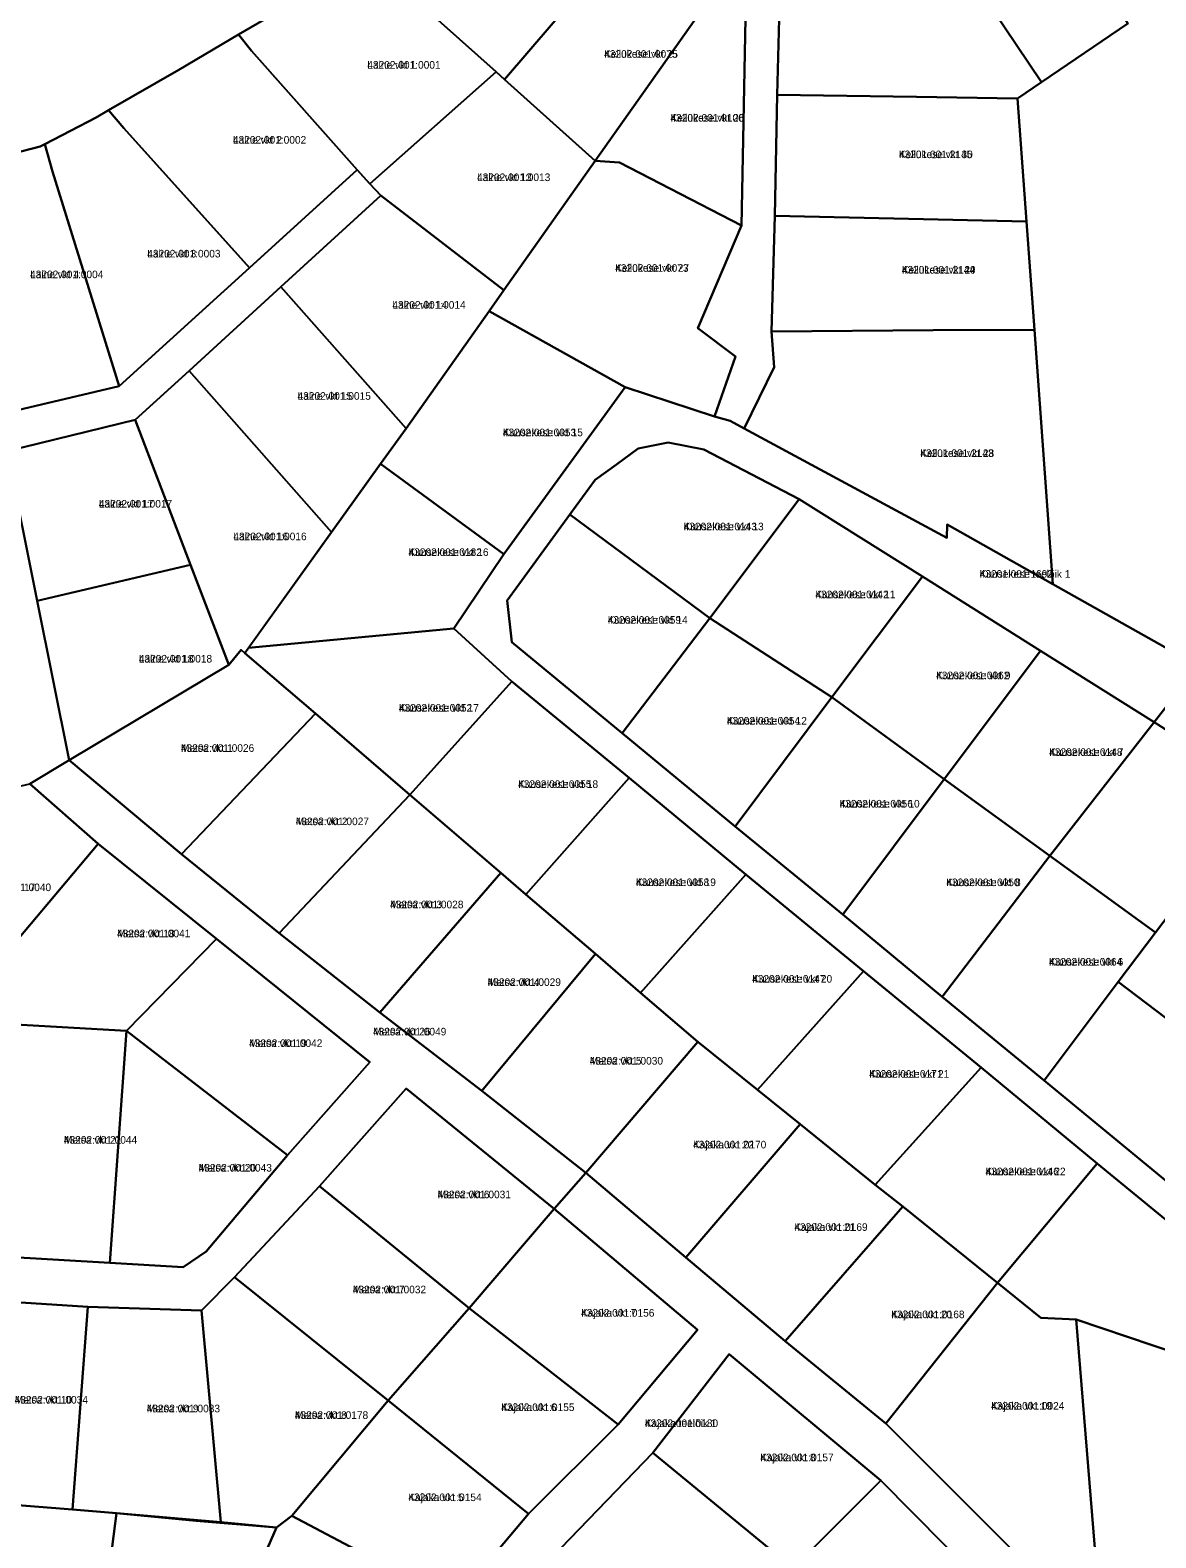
# Model space of a CAD drawing. Extents: x 661852 to 683758, y 6469495 to 6482657.
# Drawn here: x 665584.5 to 665807.3, y 6471214 to 6471512.2 of the extents above; entities that cross this region are included whole.
import ezdxf

# ---------------------------------------------------------------- set-up
doc = ezdxf.new("R2010")
doc.units = 0
for name, color, linetype in [('L_AADRESS', 7, 'Continuous'), ('PIIR', 7, 'Continuous'), ('TUNNUS', 7, 'Continuous')]:
    doc.layers.add(name, color=color, linetype=linetype)

msp = doc.modelspace()

# ---------------------------------------------------------------- linework, layer by layer
at = {"layer": 'PIIR'}
for points in [[(665767.41, 6471527.59), (665747.38, 6471557.17), (665765.56, 6471568.66), (665785.32, 6471538.68), (665801.72, 6471513.57), (665784.67, 6471501.96)], [(665650.95, 6471536.39), (665692.2, 6471535.2), (665697.63, 6471524.99), (665678.39, 6471502.49), (665676.71, 6471503.99), (665654.4, 6471524), (665648.12, 6471529.63)], [(665649.26, 6471484.59), (665628.33, 6471508.17), (665625.77, 6471511.37), (665630.74, 6471514.31), (665642.13, 6471521.05), (665647.12, 6471527.24), (665648.12, 6471529.63), (665654.4, 6471524), (665676.71, 6471503.99), (665651.77, 6471481.85)], [(665732.32, 6471499.43), (665733.06, 6471527.07), (665763.85, 6471523.8), (665767.41, 6471527.59), (665784.67, 6471501.96), (665779.93, 6471498.71), (665759.93, 6471499.05)], [(665706.87, 6471518.76), (665717.83, 6471516.78), (665696.35, 6471486.42), (665678.39, 6471502.49), (665697.63, 6471524.99)], [(665726.1, 6471514.53), (665725.28, 6471473.59), (665701.12, 6471486.1), (665696.35, 6471486.42), (665717.83, 6471516.78)], [(665603.07, 6471492.84), (665600.05, 6471496.41), (665613.96, 6471504.38), (665625.77, 6471511.37), (665628.33, 6471508.17), (665649.26, 6471484.59), (665627.94, 6471465.25)], [(665676.71, 6471503.99), (665678.39, 6471502.49), (665696.35, 6471486.42), (665678.26, 6471460.82), (665653.91, 6471479.55), (665651.77, 6471481.85)], [(665731.9, 6471475.54), (665732.32, 6471499.43), (665759.93, 6471499.05), (665779.93, 6471498.71), (665781.69, 6471474.42), (665761.28, 6471474.89)], [(665588.95, 6471484.26), (665587.44, 6471489.72), (665597.56, 6471494.98), (665600.05, 6471496.41), (665603.07, 6471492.84), (665627.94, 6471465.25), (665602.13, 6471441.82)], [(665567.9, 6471479.65), (665566.88, 6471485.09), (665579.86, 6471487.61), (665580.87, 6471487.8), (665586.53, 6471489.24), (665587.44, 6471489.72), (665588.95, 6471484.26), (665602.13, 6471441.82), (665577.19, 6471435.94)], [(665716.61, 6471453.3), (665724.08, 6471447.73), (665719.92, 6471435.86), (665702.25, 6471441.65), (665675.32, 6471456.68), (665678.26, 6471460.82), (665696.35, 6471486.42), (665701.12, 6471486.1), (665725.28, 6471473.59)], [(665653.91, 6471479.55), (665678.26, 6471460.82), (665675.32, 6471456.68), (665658.92, 6471433.46), (665634.14, 6471461.5)], [(665731.23, 6471452.66), (665731.9, 6471475.54), (665761.28, 6471474.89), (665781.69, 6471474.42), (665783.26, 6471452.99), (665763.19, 6471452.93)], [(665634.14, 6471461.5), (665658.92, 6471433.46), (665653.87, 6471426.44), (665644.14, 6471412.92), (665615.96, 6471444.88)], [(665678.24, 6471408.58), (665653.87, 6471426.44), (665658.92, 6471433.46), (665675.32, 6471456.68), (665702.25, 6471441.65)], [(665731.74, 6471445.57), (665731.23, 6471452.66), (665763.19, 6471452.93), (665783.26, 6471452.99), (665786.91, 6471402.68), (665765.95, 6471414.45), (665765.91, 6471411.86), (665725.82, 6471433.45)], [(665615.96, 6471444.88), (665644.14, 6471412.92), (665626.98, 6471389.05), (665626.3, 6471389.71), (665623.87, 6471386.74), (665616.25, 6471406.48), (665605.33, 6471435.17)], [(665605.33, 6471435.17), (665616.25, 6471406.48), (665585.91, 6471399.37), (665579.99, 6471428.95)], [(665736.69, 6471419.46), (665719, 6471395.91), (665691.34, 6471416.47), (665696.3, 6471423.31), (665700.53, 6471426.35), (665704.86, 6471429.52), (665710.78, 6471430.72), (665717.85, 6471429.29)], [(665678.24, 6471408.58), (665668.35, 6471393.93), (665627.71, 6471390.06), (665644.14, 6471412.92), (665653.87, 6471426.44)], [(665761.08, 6471404.21), (665743.15, 6471380.29), (665719, 6471395.91), (665736.69, 6471419.46)], [(665719, 6471395.91), (665701.64, 6471373.22), (665679.85, 6471391.22), (665678.91, 6471399.42), (665691.34, 6471416.47)], [(665616.25, 6471406.48), (665623.87, 6471386.74), (665592.21, 6471367.86), (665585.91, 6471399.37)], [(665784.43, 6471389.46), (665765.38, 6471364.08), (665743.15, 6471380.29), (665761.08, 6471404.21)], [(665701.64, 6471373.22), (665719, 6471395.91), (665743.15, 6471380.29), (665724.02, 6471354.75)], [(665679.82, 6471383.43), (665659.67, 6471361), (665640.99, 6471377.06), (665626.98, 6471389.05), (665627.71, 6471390.06), (665668.35, 6471393.93)], [(665623.87, 6471386.74), (665626.3, 6471389.71), (665626.98, 6471389.05), (665640.99, 6471377.06), (665614.48, 6471349.28), (665592.21, 6471367.86)], [(665806.96, 6471375.36), (665786.3, 6471348.93), (665765.38, 6471364.08), (665784.43, 6471389.46)], [(665703.05, 6471364.38), (665682.62, 6471341.3), (665677.69, 6471345.58), (665659.67, 6471361), (665679.82, 6471383.43)], [(665724.02, 6471354.75), (665743.15, 6471380.29), (665765.38, 6471364.08), (665745.33, 6471337.3)], [(665806.96, 6471375.36), (665810.63, 6471380.1), (665831.53, 6471367), (665828.25, 6471361.76)], [(665640.99, 6471377.06), (665659.67, 6471361), (665633.83, 6471333.61), (665614.48, 6471349.28)], [(665786.3, 6471348.93), (665806.96, 6471375.36), (665828.25, 6471361.76), (665814.63, 6471343.56), (665807.23, 6471333.77)], [(665568.64, 6471316.51), (665560.76, 6471332.69), (665550.36, 6471355.42), (665584.49, 6471363.17), (665597.98, 6471351.32)], [(665726.17, 6471345.23), (665705.33, 6471321.82), (665696.39, 6471329.53), (665682.62, 6471341.3), (665703.05, 6471364.38)], [(665765.01, 6471321.06), (665745.33, 6471337.3), (665765.38, 6471364.08), (665786.3, 6471348.93)], [(665659.67, 6471361), (665677.69, 6471345.58), (665653.72, 6471317.92), (665633.83, 6471333.61)], [(665603.57, 6471314.33), (665581.61, 6471315.6), (665568.64, 6471316.51), (665597.98, 6471351.32), (665621.41, 6471332.54)], [(665765.01, 6471321.06), (665786.3, 6471348.93), (665807.23, 6471333.77), (665799.84, 6471324.03), (665785.19, 6471304.5)], [(665677.69, 6471345.58), (665682.62, 6471341.3), (665696.39, 6471329.53), (665673.89, 6471302.45), (665653.72, 6471317.92)], [(665749.45, 6471326.15), (665728.42, 6471302.64), (665716.62, 6471312.13), (665705.33, 6471321.82), (665726.17, 6471345.23)], [(665831.52, 6471299.93), (665799.84, 6471324.03), (665807.23, 6471333.77), (665814.63, 6471343.56), (665846.4, 6471320.17)], [(665621.41, 6471332.54), (665651.73, 6471308.11), (665635.45, 6471289.71), (665603.57, 6471314.33)], [(665696.39, 6471329.53), (665705.33, 6471321.82), (665716.62, 6471312.13), (665694.47, 6471286.2), (665673.89, 6471302.45)], [(665772.7, 6471307.04), (665751.76, 6471283.88), (665736.91, 6471295.86), (665728.42, 6471302.64), (665749.45, 6471326.15)], [(665785.19, 6471304.5), (665799.84, 6471324.03), (665831.52, 6471299.93), (665818.1, 6471281.58), (665813.19, 6471281.43)], [(665603.57, 6471314.33), (665600.27, 6471268.42), (665578.82, 6471269.7), (665581.61, 6471315.6)], [(665635.45, 6471289.71), (665619.35, 6471270.68), (665614.79, 6471267.55), (665600.27, 6471268.42), (665603.57, 6471314.33)], [(665694.47, 6471286.2), (665716.62, 6471312.13), (665728.42, 6471302.64), (665736.91, 6471295.86), (665714.3, 6471269.45)], [(665795.67, 6471288.1), (665775.91, 6471264.46), (665757.18, 6471279.57), (665751.76, 6471283.88), (665772.7, 6471307.04)], [(665688.21, 6471279.09), (665671.41, 6471259.46), (665641.77, 6471283.58), (665658.96, 6471302.93)], [(665736.91, 6471295.86), (665751.76, 6471283.88), (665757.18, 6471279.57), (665733.93, 6471252.93), (665714.3, 6471269.45)], [(665714.3, 6471269.45), (665733.93, 6471252.93), (665753.87, 6471236.65), (665786.46, 6471204.1), (665778.11, 6471199.83), (665752.84, 6471225.36), (665722.84, 6471250.36), (665707.76, 6471230.82), (665689.55, 6471212), (665673.66, 6471193.13), (665659.29, 6471160.21), (665644.8, 6471126.48), (665634.26, 6471096.23), (665627.62, 6471097.4), (665625.85, 6471097.9), (665636.04, 6471128.1), (665646.89, 6471154.75), (665657.32, 6471180.05), (665668.49, 6471201.39), (665683.13, 6471218.76), (665700.9, 6471236.46), (665716.59, 6471255.2), (665688.21, 6471279.09), (665694.47, 6471286.2)], [(665775.91, 6471264.46), (665795.67, 6471288.1), (665811.05, 6471275.45), (665821.22, 6471275.59), (665825.74, 6471282.18), (665844.79, 6471265.44), (665857.96, 6471249.95), (665822.01, 6471246.94), (665791.48, 6471257.24), (665784.52, 6471257.54)], [(665641.77, 6471283.58), (665671.41, 6471259.46), (665655.39, 6471241.21), (665624.99, 6471265.56)], [(665757.18, 6471279.57), (665775.91, 6471264.46), (665753.87, 6471236.65), (665733.93, 6471252.93)], [(665716.59, 6471255.2), (665700.9, 6471236.46), (665671.41, 6471259.46), (665688.21, 6471279.09)], [(665622.24, 6471217.12), (665618.42, 6471258.97), (665624.99, 6471265.56), (665655.39, 6471241.21), (665636.32, 6471218.41), (665633.26, 6471216.06)], [(665795.48, 6471208.75), (665786.46, 6471204.1), (665753.87, 6471236.65), (665775.91, 6471264.46), (665784.52, 6471257.54), (665791.48, 6471257.24)], [(665595.91, 6471259.7), (665592.93, 6471219.62), (665567.02, 6471221.71), (665569.35, 6471261.41)], [(665622.24, 6471217.12), (665601.59, 6471218.91), (665592.93, 6471219.62), (665595.91, 6471259.7), (665618.42, 6471258.97)], [(665683.13, 6471218.76), (665655.39, 6471241.21), (665671.41, 6471259.46), (665700.9, 6471236.46)], [(665673.21, 6471021.95), (665666.19, 6471048.71), (665665.1, 6471052.86), (665682.16, 6471081.03), (665690.7, 6471095.45), (665711.53, 6471121.88), (665732.89, 6471142.71), (665748.91, 6471158.46), (665767.33, 6471175.55), (665784.18, 6471192.99), (665790.82, 6471197.44), (665786.46, 6471204.1), (665795.48, 6471208.75), (665791.48, 6471257.24), (665822.01, 6471246.94), (665857.96, 6471249.95), (665886.27, 6471252.42), (665904.61, 6471135.01), (665918.06, 6471004.84), (665868.57, 6471000.65), (665770.3, 6470992.05), (665738.2, 6470995.8), (665701.71, 6471016.32), (665681.89, 6471021.95)], [(665735.52, 6471208), (665707.76, 6471230.82), (665722.84, 6471250.36), (665752.84, 6471225.36)], [(665668.49, 6471201.39), (665636.32, 6471218.41), (665655.39, 6471241.21), (665683.13, 6471218.76)], [(665717.76, 6471190), (665689.55, 6471212), (665707.76, 6471230.82), (665735.52, 6471208)], [(665778.11, 6471199.83), (665761.41, 6471181.69), (665735.52, 6471208), (665752.84, 6471225.36)], [(665592.93, 6471219.62), (665601.59, 6471218.91), (665592.24, 6471146.2), (665573.04, 6471147.84), (665560.82, 6471148.88), (665567.02, 6471221.71)], [(665601.59, 6471218.91), (665617.37, 6471217.4), (665633.26, 6471216.06), (665624.29, 6471195.51), (665614.87, 6471168.6), (665614.07, 6471166.22), (665595.71, 6471144.81), (665591.46, 6471140.08), (665592.24, 6471146.2)], [(665624.29, 6471195.51), (665633.26, 6471216.06), (665636.32, 6471218.41), (665668.49, 6471201.39), (665657.32, 6471180.05)]]:
    msp.add_lwpolyline(points, close=True, dxfattribs=at)
for points in [[(665733.06, 6471527.07), (665732.32, 6471499.43), (665731.9, 6471475.54), (665731.23, 6471452.66), (665731.74, 6471445.57), (665725.82, 6471433.45), (665723.03, 6471434.97), (665719.92, 6471435.86), (665724.08, 6471447.73), (665716.61, 6471453.3), (665725.28, 6471473.59), (665726.1, 6471514.53)], [(665630.74, 6471514.31), (665625.77, 6471511.37), (665613.96, 6471504.38), (665600.05, 6471496.41), (665597.56, 6471494.98), (665587.44, 6471489.72), (665586.53, 6471489.24), (665580.87, 6471487.8), (665579.86, 6471487.61), (665566.88, 6471485.09), (665550.19, 6471481.86), (665543.02, 6471480.46), (665529.63, 6471477.87), (665521.08, 6471476.73), (665519.55, 6471476.53), (665496.22, 6471482.17), (665463.23, 6471490.15), (665450.93, 6471494.06), (665424.14, 6471502.96)], [(666036.05, 6471461.75), (665876.13, 6471458.62), (665891.47, 6471332.56), (665875.88, 6471341.53), (665867.2, 6471399.74), (665849.26, 6471394.98), (665816.79, 6471387.86), (665814.31, 6471387.21), (665786.91, 6471402.68), (665783.26, 6471452.99), (665781.69, 6471474.42), (665779.93, 6471498.71), (665784.67, 6471501.96), (665801.72, 6471513.57)], [(665577.19, 6471435.94), (665602.13, 6471441.82), (665627.94, 6471465.25), (665649.26, 6471484.59), (665651.77, 6471481.85), (665653.91, 6471479.55), (665634.14, 6471461.5), (665615.96, 6471444.88), (665605.33, 6471435.17), (665579.99, 6471428.95), (665585.91, 6471399.37), (665592.21, 6471367.86), (665584.49, 6471363.17)], [(665811.05, 6471275.45), (665795.67, 6471288.1), (665772.7, 6471307.04), (665749.45, 6471326.15), (665726.17, 6471345.23), (665703.05, 6471364.38), (665679.82, 6471383.43), (665668.35, 6471393.93), (665678.24, 6471408.58), (665702.25, 6471441.65), (665719.92, 6471435.86), (665723.03, 6471434.97), (665725.82, 6471433.45), (665765.91, 6471411.86), (665765.95, 6471414.45), (665786.91, 6471402.68), (665814.31, 6471387.21)], [(665810.63, 6471380.1), (665806.96, 6471375.36), (665784.43, 6471389.46), (665761.08, 6471404.21), (665736.69, 6471419.46), (665717.85, 6471429.29), (665710.78, 6471430.72), (665704.86, 6471429.52), (665700.53, 6471426.35), (665696.3, 6471423.31), (665691.34, 6471416.47), (665678.91, 6471399.42), (665679.85, 6471391.22), (665701.64, 6471373.22), (665724.02, 6471354.75), (665745.33, 6471337.3), (665765.01, 6471321.06), (665785.19, 6471304.5), (665813.19, 6471281.43)], [(665578.82, 6471269.7), (665600.27, 6471268.42), (665614.79, 6471267.55), (665619.35, 6471270.68), (665635.45, 6471289.71), (665651.73, 6471308.11), (665621.41, 6471332.54), (665597.98, 6471351.32), (665584.49, 6471363.17), (665592.21, 6471367.86), (665614.48, 6471349.28), (665633.83, 6471333.61), (665653.72, 6471317.92), (665673.89, 6471302.45), (665694.47, 6471286.2), (665688.21, 6471279.09), (665658.96, 6471302.93), (665641.77, 6471283.58), (665624.99, 6471265.56), (665618.42, 6471258.97), (665595.91, 6471259.7), (665569.35, 6471261.41)]]:
    msp.add_lwpolyline(points, dxfattribs=at)

# ---------------------------------------------------------------- texts
at = {"layer": 'L_AADRESS'}
for s, p in [('Laine vkt 1', (665651.24, 6471504.63)), ('Kellukese vkt 25', (665698.11, 6471506.79)), ('Kellukese vkt 26', (665711.23, 6471494.16)), ('Laine vkt 2', (665624.65, 6471489.8)), ('Kellukese vkt 30', (665756.44, 6471486.93)), ('Laine vkt 13', (665672.95, 6471482.4)), ('Laine vkt 3', (665607.69, 6471467.29)), ('Laine vkt 4', (665584.51, 6471463.19)), ('Kellukese vkt 27', (665700.3, 6471464.45)), ('Kellukese vkt 29', (665757.01, 6471464.1)), ('Laine vkt 14', (665656.2, 6471457.16)), ('Laine vkt 15', (665637.44, 6471439.14)), ('Kuusekese vkt 15', (665678.06, 6471431.93)), ('Kellukese vkt 28', (665760.67, 6471427.83)), ('Laine vkt 17', (665598.12, 6471417.82)), ('Kuusekese vkt 13', (665713.83, 6471413.32)), ('Laine vkt 16', (665624.73, 6471411.36)), ('Kuusekese vkt 16', (665659.4, 6471408.25)), ('Kuusekese teelõik 1', (665772.41, 6471403.94)), ('Kuusekese vkt 11', (665739.9, 6471399.88)), ('Kuusekese vkt 14', (665698.81, 6471394.84)), ('Laine vkt 18', (665606.03, 6471387.17)), ('Kuusekese vkt 9', (665763.79, 6471383.87)), ('Kuusekese vkt 17', (665657.49, 6471377.46)), ('Kuusekese vkt 12', (665722.39, 6471374.9)), ('Metsa vkt 1', (665614.36, 6471369.5)), ('Kuusekese vkt 7', (665786.17, 6471368.7)), ('Kuusekese vkt 18', (665681.08, 6471362.37)), ('Kuusekese vkt 10', (665744.7, 6471358.49)), ('Metsa vkt 2', (665637.07, 6471355)), ('Metsa vkt 17', (665574.17, 6471341.95)), ('Kuusekese vkt 19', (665704.39, 6471342.95)), ('Kuusekese vkt 8', (665765.81, 6471342.94)), ('Metsa vkt 3', (665655.76, 6471338.56)), ('Metsa vkt 18', (665601.72, 6471332.82)), ('Kuusekese vkt 6', (665786.12, 6471327.22)), ('Metsa vkt 4', (665675.05, 6471323.2)), ('Kuusekese vkt 20', (665727.39, 6471323.85)), ('Metsa vkt 19', (665627.85, 6471311.12)), ('Metsa vkt 26', (665652.37, 6471313.41)), ('Metsa vkt 5', (665695.25, 6471307.64)), ('Kuusekese vkt 21', (665750.56, 6471305.04)), ('Metsa vkt 21', (665591.2, 6471292)), ('Kajaka vkt 22', (665715.69, 6471291.06)), ('Metsa vkt 20', (665617.86, 6471286.48)), ('Kuusekese vkt 22', (665773.58, 6471285.75)), ('Metsa vkt 6', (665665.16, 6471281.2)), ('Kajaka vkt 21', (665735.74, 6471274.75)), ('Metsa vkt 7', (665648.37, 6471262.4)), ('Kajaka vkt 7', (665693.55, 6471257.78)), ('Kajaka vkt 20', (665754.92, 6471257.48)), ('Metsa vkt 10', (665581.46, 6471240.59)), ('Kajaka vkt 19', (665774.67, 6471239.39)), ('Metsa vkt 9', (665607.59, 6471238.86)), ('Metsa vkt 8', (665636.91, 6471237.56)), ('Kajaka vkt 6', (665677.74, 6471239.11)), ('Kajaka teelõik 1', (665706.16, 6471235.95)), ('Kajaka vkt 8', (665729.01, 6471229.18)), ('Kajaka vkt 5', (665659.36, 6471221.3))]:
    msp.add_text(s, height=1.5, dxfattribs=at).set_placement(p)
at = {"layer": 'TUNNUS'}
for s, p in [('43202:001:0001', (665651.24, 6471504.63)), ('43202:001:0075', (665698.11, 6471506.79)), ('43202:001:0106', (665711.23, 6471494.16)), ('43202:001:0002', (665624.65, 6471489.8)), ('43201:001:2145', (665756.44, 6471486.93)), ('43202:001:0013', (665672.95, 6471482.4)), ('43202:001:0003', (665607.69, 6471467.29)), ('43202:001:0004', (665584.51, 6471463.19)), ('43202:001:0073', (665700.3, 6471464.45)), ('43201:001:2144', (665757.01, 6471464.1)), ('43202:001:0014', (665656.2, 6471457.16)), ('43202:001:0015', (665637.44, 6471439.14)), ('43202:001:0053', (665678.06, 6471431.93)), ('43201:001:2143', (665760.67, 6471427.83)), ('43202:001:0017', (665598.12, 6471417.82)), ('43202:001:0143', (665713.83, 6471413.32)), ('43202:001:0016', (665624.73, 6471411.36)), ('43202:001:0182', (665659.4, 6471408.25)), ('43201:001:1692', (665772.41, 6471403.94)), ('43202:001:0142', (665739.9, 6471399.88)), ('43202:001:0059', (665698.81, 6471394.84)), ('43202:001:0018', (665606.03, 6471387.17)), ('43202:001:0062', (665763.79, 6471383.87)), ('43202:001:0052', (665657.49, 6471377.46)), ('43202:001:0054', (665722.39, 6471374.9)), ('43202:001:0026', (665614.36, 6471369.5)), ('43202:001:0148', (665786.17, 6471368.7)), ('43202:001:0055', (665681.08, 6471362.37)), ('43202:001:0056', (665744.7, 6471358.49)), ('43202:001:0027', (665637.07, 6471355)), ('43202:001:0040', (665574.17, 6471341.95)), ('43202:001:0058', (665704.39, 6471342.95)), ('43202:001:0050', (665765.81, 6471342.94)), ('43202:001:0028', (665655.76, 6471338.56)), ('43202:001:0041', (665601.72, 6471332.82)), ('43202:001:0064', (665786.12, 6471327.22)), ('43202:001:0029', (665675.05, 6471323.2)), ('43202:001:0147', (665727.39, 6471323.85)), ('43202:001:0042', (665627.85, 6471311.12)), ('43202:001:0049', (665652.37, 6471313.41)), ('43202:001:0030', (665695.25, 6471307.64)), ('43202:001:0171', (665750.56, 6471305.04)), ('43202:001:0044', (665591.2, 6471292)), ('43202:001:0170', (665715.69, 6471291.06)), ('43202:001:0043', (665617.86, 6471286.48)), ('43202:001:0146', (665773.58, 6471285.75)), ('43202:001:0031', (665665.16, 6471281.2)), ('43202:001:0169', (665735.74, 6471274.75)), ('43202:001:0032', (665648.37, 6471262.4)), ('43202:001:0156', (665693.55, 6471257.78)), ('43202:001:0168', (665754.92, 6471257.48)), ('43202:001:0034', (665581.46, 6471240.59)), ('43202:001:0024', (665774.67, 6471239.39)), ('43202:001:0033', (665607.59, 6471238.86)), ('43202:001:0178', (665636.91, 6471237.56)), ('43202:001:0155', (665677.74, 6471239.11)), ('43202:001:0180', (665706.16, 6471235.95)), ('43202:001:0157', (665729.01, 6471229.18)), ('43202:001:0154', (665659.36, 6471221.3))]:
    msp.add_text(s, height=1.5, dxfattribs=at).set_placement(p)

doc.saveas('drawing.dxf')
